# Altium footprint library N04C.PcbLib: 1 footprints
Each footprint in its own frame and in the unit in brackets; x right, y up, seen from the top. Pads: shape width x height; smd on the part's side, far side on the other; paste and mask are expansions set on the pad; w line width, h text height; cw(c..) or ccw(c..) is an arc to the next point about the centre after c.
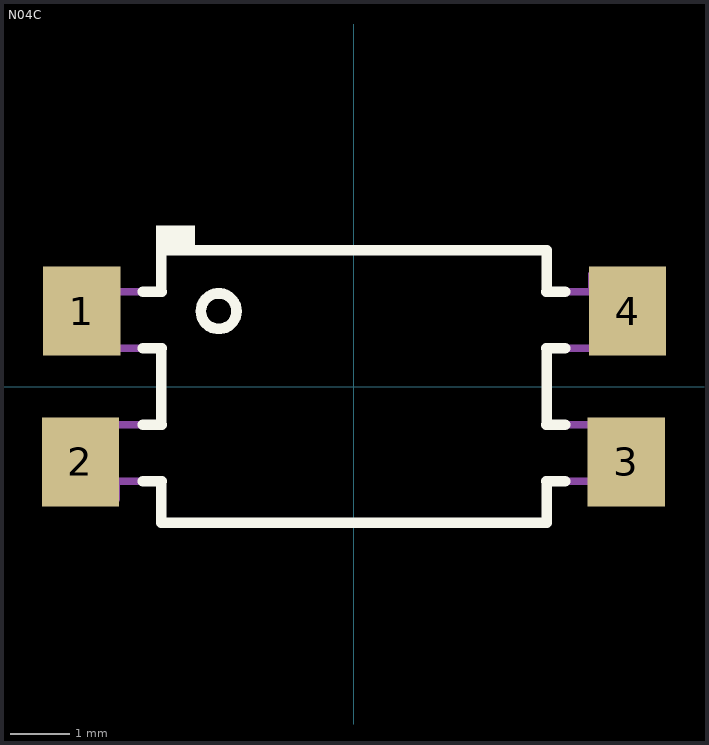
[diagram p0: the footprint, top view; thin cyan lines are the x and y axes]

## N04C [mm] "FAIRCHILD"
height 4
pads (4):
  rect 1.3x1.5 smd mask+0.065: 1(-4.587,1.27) 2(-4.612,-1.27) 3(4.588,-1.27) 4(4.613,1.27)
Top Overlay:
  rectangle: -3.339,2.294 -2.68,2.718
  lines w0.178: -3.556,-1.596 -3.241,-1.596 ; -3.556,-0.646 -3.241,-0.646 ; -3.556,0.644 -3.241,0.644 ; -3.556,1.594 -3.241,1.594 ; -3.25,-1.596 -3.25,-2.296 3.25,-2.296 3.25,-1.596 ; -3.25,-0.646 -3.25,0.644 ; -3.25,1.594 -3.25,2.294 3.25,2.294 3.25,1.594 ; 3.241,-1.596 3.556,-1.596 ; 3.241,-0.646 3.556,-0.646 ; 3.241,0.644 3.556,0.644 ; 3.241,1.594 3.556,1.594 ; 3.25,-0.646 3.25,0.644 ; -2.58,1.269 cw(c-2.28,1.269) -1.98,1.269 cw(c-2.28,1.269) -2.58,1.269
M5 Assembly Top:
  lines w0.127: -4.007,-1.596 -4.007,-1.896 -4.267,-1.896 ; -4.007,1.594 -4.007,1.894 -4.267,1.894 ; -3.25,-1.596 -3.25,-2.296 3.25,-2.296 3.25,-1.596 ; -3.25,-0.646 -3.25,0.644 ; -3.25,1.594 -3.25,2.294 3.25,2.294 3.25,1.594 ; -3.241,-1.596 -3.837,-1.596 -4.192,-1.596 -4.267,-1.596 -4.267,-1.896 ; -3.241,-0.646 -3.837,-0.646 -4.192,-0.646 -4.326,-0.646 -4.424,-0.646 -4.71,-0.646 -5.08,-1.016 -5.08,-1.526 -4.71,-1.896 -4.424,-1.896 -4.326,-1.896 -4.267,-1.896 ; -3.241,0.644 -3.837,0.644 -4.192,0.644 -4.326,0.644 -4.424,0.644 -4.71,0.644 -5.08,1.014 -5.08,1.524 -4.71,1.894 -4.424,1.894 -4.326,1.894 -4.267,1.894 ; -3.241,1.594 -3.837,1.594 -4.192,1.594 -4.267,1.594 -4.267,1.894 ; 3.241,-1.596 3.837,-1.596 4.192,-1.596 4.267,-1.596 4.267,-1.896 ; 3.241,-0.646 3.837,-0.646 4.192,-0.646 4.326,-0.646 4.424,-0.646 4.71,-0.646 5.08,-1.016 5.08,-1.526 4.71,-1.896 4.424,-1.896 4.326,-1.896 4.267,-1.896 ; 3.241,0.644 3.837,0.644 4.192,0.644 4.326,0.644 4.424,0.644 4.71,0.644 5.08,1.014 5.08,1.524 4.71,1.894 4.424,1.894 4.326,1.894 4.267,1.894 ; 3.241,1.594 3.837,1.594 4.192,1.594 4.267,1.594 4.267,1.894 ; 3.25,-0.646 3.25,0.644 ; 4.007,-1.596 4.007,-1.896 4.267,-1.896 ; 4.007,1.594 4.007,1.894 4.267,1.894 ; -2.58,1.269 ccw(c-2.28,1.269) -1.98,1.269 ccw(c-2.28,1.269) -2.58,1.269
  text ".Designator" at -1.626,-0.66 h0.89
3D body: height 3.87, standoff 0.02, extent -5.08,-2.295 5.08,2.295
